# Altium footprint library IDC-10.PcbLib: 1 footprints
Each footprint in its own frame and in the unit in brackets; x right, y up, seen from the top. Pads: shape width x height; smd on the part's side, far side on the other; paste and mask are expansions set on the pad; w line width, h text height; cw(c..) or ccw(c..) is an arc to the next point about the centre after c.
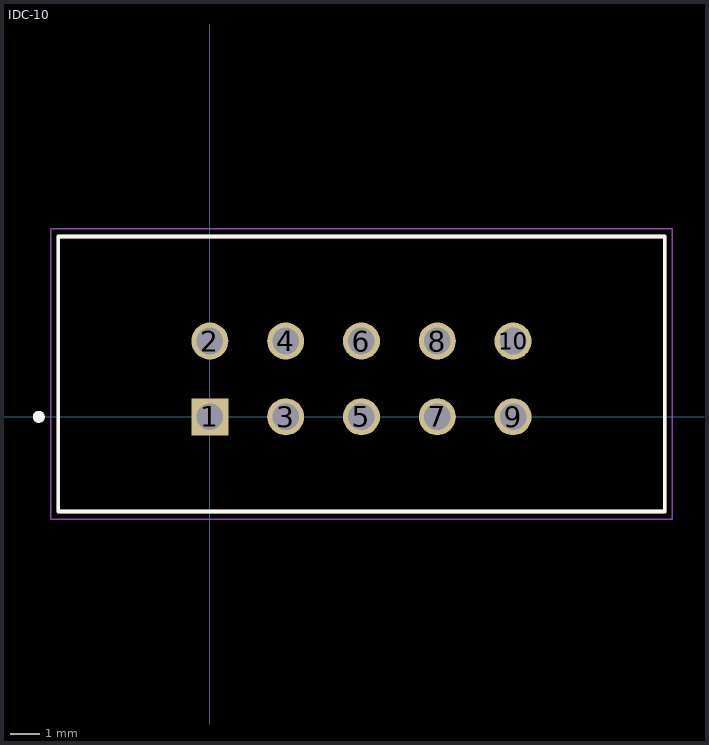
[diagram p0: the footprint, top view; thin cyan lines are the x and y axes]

## IDC-10 [mm]
pads (10):
  rect 1.24x1.24 hole 0.89: 1(0,0)
  round 1.24 hole 0.89: 2(0,2.54) 3(2.54,0) 4(2.54,2.54) 5(5.08,0) 6(5.08,2.54) 7(7.62,0) 8(7.62,2.54) 9(10.16,0) 10(10.16,2.54)
Top Overlay:
  circle w0.2: c-5.73,0 r0.1
  lines w0.127: -5.08,-3.175 -5.08,6.045 15.24,6.045 15.24,-3.175 -5.08,-3.175
Mechanical 13:
  circle w0.2: c-5.73,0 r0.1
  lines w0.127: -5.08,-3.175 -5.08,6.045 ; -5.08,-3.175 15.24,-3.175 ; -5.08,-3.175 -5.08,6.045 ; -5.08,6.045 15.24,6.045 ; -5.08,6.045 15.24,6.045 ; 15.24,-3.175 15.24,6.045 ; 15.24,-3.175 15.24,6.045
Mechanical 15:
  lines w0.05: -5.33,-3.425 -5.33,6.295 15.49,6.295 15.49,-3.425 -5.33,-3.425
3D body "IDC-10.STEP": height 8.89, standoff -2.92, extent -5.08,-3.048 15.24,6.172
